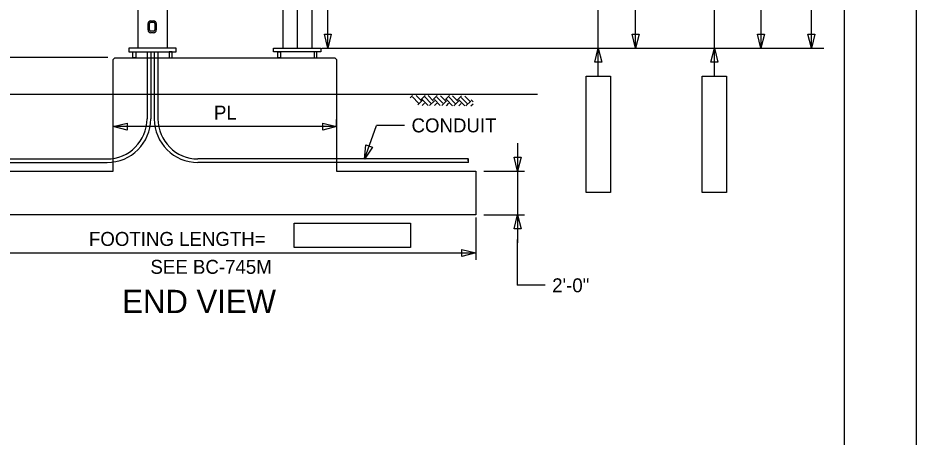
# Model space of a CAD drawing. Extents: x 3831399 to 3833095, y 499014 to 500202.
# Drawn here: x 3832893.8 to 3833081.2, y 499745.2 to 499832.5 of the extents above; entities that cross this region are included whole.
import ezdxf

# ---------------------------------------------------------------- set-up
doc = ezdxf.new("R2010")
doc.units = 0
for name, color, linetype in [('0-ANCHOR', 7, 'Continuous'), ('0-foundation', 7, 'Continuous'), ('0-truss', 7, 'Continuous'), ('2', 7, 'Continuous'), ('CenterLine', 7, 'Continuous'), ('Default', 7, 'Continuous'), ('DIM TXT', 7, 'Continuous'), ('PLT-BNDY', 7, 'Continuous'), ('structure', 7, 'Continuous'), ('XEG', 7, 'Continuous')]:
    doc.layers.add(name, color=color, linetype=linetype)

msp = doc.modelspace()

# ---------------------------------------------------------------- linework, layer by layer
at = {"layer": '0-ANCHOR'}
for p, q in [((3832917.82, 499825.49), (3832918.38, 499825.49)), ((3832917.82, 499824.26), (3832917.82, 499825.49)), ((3832918.38, 499825.49), (3832918.38, 499824.26)), ((3832925.97, 499825.49), (3832925.4, 499825.49)), ((3832925.4, 499825.49), (3832925.4, 499824.26)), ((3832925.97, 499824.26), (3832925.97, 499825.49)), ((3832948, 499825.49), (3832948.57, 499825.49)), ((3832948, 499824.26), (3832948, 499825.49)), ((3832948.57, 499825.49), (3832948.57, 499824.26)), ((3832956.16, 499825.49), (3832955.59, 499825.49)), ((3832955.59, 499825.49), (3832955.59, 499824.26)), ((3832956.16, 499824.26), (3832956.16, 499825.49)), ((3832918.38, 499824.26), (3832917.82, 499824.26)), ((3832925.4, 499824.26), (3832925.97, 499824.26)), ((3832948.57, 499824.26), (3832948, 499824.26)), ((3832955.59, 499824.26), (3832956.16, 499824.26))]:
    msp.add_line(p, q, dxfattribs=at)
at = {"layer": '0-foundation'}
for p, q in [((3832920.75, 499825.49), (3832920.75, 499811.51)), ((3832921.51, 499825.49), (3832921.51, 499811.51)), ((3832922.27, 499825.49), (3832922.27, 499811.51)), ((3832923.03, 499825.49), (3832923.03, 499811.51)), ((3832913.67, 499823.88), (3832914.05, 499824.26)), ((3832913.67, 499815.55), (3832913.67, 499823.88)), ((3832914.05, 499824.26), (3832959.92, 499824.26)), ((3832959.92, 499824.26), (3832960.3, 499823.88)), ((3832960.3, 499823.88), (3832960.3, 499815.55)), ((3832913.67, 499800.6), (3832913.67, 499815.55)), ((3832960.3, 499815.55), (3832960.3, 499800.6)), ((3832886.24, 499803.17), (3832912.41, 499803.17)), ((3832886.24, 499802.41), (3832912.41, 499802.41)), ((3832987.73, 499803.17), (3832931.37, 499803.17)), ((3832987.73, 499802.41), (3832931.37, 499802.41)), ((3832884.67, 499800.6), (3832913.67, 499800.6)), ((3832960.3, 499800.6), (3832989.31, 499800.6)), ((3832989.31, 499800.6), (3832989.31, 499791.5)), ((3832989.31, 499791.5), (3832884.67, 499791.5))]:
    msp.add_line(p, q, dxfattribs=at)
for centre, radius, start, end in [((3832912.41, 499811.51), 9.1, 270, 0), ((3832912.41, 499811.51), 8.34, 270, 0), ((3832931.37, 499811.51), 9.1, 180, 270), ((3832931.37, 499811.51), 8.34, 180, 270), ((3832987.87, 499802.98), 0.237, 126.8699, 233.1301), ((3832987.59, 499802.98), 0.237, 306.8699, 53.1301), ((3832987.59, 499802.6), 0.237, 306.8699, 53.1301)]:
    msp.add_arc(centre, radius, start, end, dxfattribs=at)
at = {"layer": '0-truss'}
for p, q in [((3832949.05, 499938.68), (3832949.05, 499826.25)), ((3832955.11, 499938.68), (3832955.11, 499826.25)), ((3832918.86, 499844.47), (3832918.86, 499826.25)), ((3832924.92, 499844.47), (3832924.92, 499826.25)), ((3832926.82, 499826.25), (3832916.96, 499826.25)), ((3832916.96, 499826.25), (3832916.96, 499825.49)), ((3832916.96, 499825.49), (3832926.82, 499825.49)), ((3832926.82, 499825.49), (3832926.82, 499826.25)), ((3832947.15, 499825.49), (3832947.15, 499826.25)), ((3832947.15, 499826.25), (3832957.01, 499826.25)), ((3832957.01, 499825.49), (3832947.15, 499825.49)), ((3832957.01, 499826.25), (3832957.01, 499825.49))]:
    msp.add_line(p, q, dxfattribs=at)
at = {"layer": '2'}
msp.add_line((3833066.16, 500187.03), (3833066.16, 499623.03), dxfattribs=at)
at = {"layer": 'CenterLine'}
msp.add_line((3832952.08, 499942.23), (3832952.08, 499826.25), dxfattribs=at)
at = {"layer": 'Default'}
for p, q in [((3833012.33, 499796.18), (3833012.33, 499820.43)), ((3833012.33, 499820.43), (3833017.42, 499820.43)), ((3833017.42, 499820.43), (3833017.42, 499796.18)), ((3833036.54, 499796.18), (3833036.54, 499820.43)), ((3833036.54, 499820.43), (3833041.63, 499820.43)), ((3833041.63, 499820.43), (3833041.63, 499796.18)), ((3833017.42, 499796.18), (3833012.33, 499796.18)), ((3833041.63, 499796.18), (3833036.54, 499796.18)), ((3832951.47, 499789.78), (3832975.72, 499789.78)), ((3832951.47, 499784.69), (3832951.47, 499789.78)), ((3832975.72, 499789.78), (3832975.72, 499784.69)), ((3832975.72, 499784.69), (3832951.47, 499784.69))]:
    msp.add_line(p, q, dxfattribs=at)
at = {"layer": 'DIM TXT'}
for p, q in [((3833022.67, 499826.25), (3833022.67, 499938.68)), ((3833048.79, 499938.68), (3833048.79, 499826.25)), ((3833059.34, 499826.25), (3833059.34, 499924.07)), ((3832958.46, 499826.25), (3832958.47, 499844.47)), ((3833014.87, 499826.25), (3833014.87, 499834.59)), ((3833039.09, 499826.25), (3833039.09, 499834.59)), ((3832957.19, 499826.25), (3833061.95, 499826.25)), ((3833014.87, 499820.43), (3833014.87, 499826.25)), ((3833039.09, 499820.43), (3833039.09, 499826.25)), ((3832912.59, 499824.28), (3832852.22, 499824.28)), ((3832911.14, 499824.28), (3832880.41, 499824.28)), ((3832913.67, 499809.89), (3832913.67, 499811.35)), ((3832960.3, 499809.89), (3832913.67, 499809.89)), ((3832960.3, 499809.89), (3832960.3, 499811.35)), ((3832966.1, 499803.13), (3832968.64, 499810.16)), ((3832974.46, 499810.16), (3832968.64, 499810.16)), ((3832998.05, 499806.42), (3832998.05, 499800.6)), ((3832991.03, 499800.6), (3832999.51, 499800.6)), ((3832998.05, 499800.6), (3832998.05, 499791.5)), ((3832998.05, 499796.05), (3832997.98, 499776.82)), ((3832989.31, 499790.98), (3832989.31, 499782.12)), ((3832991.03, 499791.5), (3832999.51, 499791.5)), ((3832998.05, 499791.5), (3832998.05, 499785.68)), ((3832884.67, 499783.58), (3832989.31, 499783.58)), ((3833003.8, 499776.82), (3832997.98, 499776.82))]:
    msp.add_line(p, q, dxfattribs=at)
for points in [[(3832959.19, 499829.16), (3832958.46, 499826.25), (3832957.74, 499829.16)], [(3833023.4, 499829.16), (3833022.67, 499826.25), (3833021.94, 499829.16)], [(3833049.52, 499829.16), (3833048.79, 499826.25), (3833048.07, 499829.16)], [(3833060.07, 499829.16), (3833059.34, 499826.25), (3833058.61, 499829.16)], [(3833014.14, 499823.34), (3833014.87, 499826.25), (3833015.6, 499823.34)], [(3833038.36, 499823.34), (3833039.09, 499826.25), (3833039.82, 499823.34)], [(3832916.58, 499809.17), (3832913.67, 499809.89), (3832916.58, 499810.62)], [(3832957.39, 499810.62), (3832960.3, 499809.89), (3832957.39, 499809.17)], [(3832967.77, 499805.62), (3832966.1, 499803.13), (3832966.4, 499806.11)], [(3832998.78, 499803.51), (3832998.05, 499800.6), (3832997.32, 499803.51)], [(3832997.32, 499788.59), (3832998.05, 499791.5), (3832998.78, 499788.59)], [(3832986.4, 499784.31), (3832989.31, 499783.58), (3832986.4, 499782.85)]]:
    msp.add_lwpolyline(points, close=True, dxfattribs=at)
at = {"layer": 'PLT-BNDY'}
msp.add_lwpolyline([(3832240.16, 500202.03), (3833081.16, 500202.03), (3833081.16, 499608.03), (3832240.16, 499608.03)], close=True, dxfattribs=at)
at = {"layer": 'structure'}
for p, q in [((3832920.98, 499830.05), (3832920.98, 499831.37)), ((3832921.26, 499830.05), (3832921.26, 499831.37)), ((3832921.54, 499831.94), (3832922.11, 499831.94)), ((3832921.54, 499831.66), (3832922.11, 499831.66)), ((3832922.4, 499831.37), (3832922.4, 499830.05)), ((3832922.68, 499831.37), (3832922.68, 499830.05)), ((3832922.11, 499829.76), (3832921.54, 499829.76)), ((3832922.11, 499829.48), (3832921.54, 499829.48))]:
    msp.add_line(p, q, dxfattribs=at)
for centre, radius, start, end in [((3832921.54, 499831.37), 0.569, 90, 180), ((3832921.54, 499831.37), 0.284, 90, 180), ((3832922.11, 499831.37), 0.569, 0, 90), ((3832922.11, 499831.37), 0.284, 0, 90), ((3832921.54, 499830.05), 0.569, 180, 270), ((3832921.54, 499830.05), 0.284, 180, 270), ((3832922.11, 499830.05), 0.569, 270, 0), ((3832922.11, 499830.05), 0.284, 270, 0)]:
    msp.add_arc(centre, radius, start, end, dxfattribs=at)
at = {"layer": 'XEG'}
for p, q in [((3832885.47, 499816.64), (3833002.21, 499816.64)), ((3832975.63, 499815.87), (3832976.16, 499816.38)), ((3832976.13, 499816.11), (3832977.39, 499814.82)), ((3832976.88, 499816.37), (3832977.9, 499815.32)), ((3832977.21, 499814.42), (3832978.15, 499815.33)), ((3832977.9, 499815.58), (3832978.74, 499816.39)), ((3832978.17, 499815.58), (3832979.4, 499814.31)), ((3832978.68, 499816.08), (3832979.94, 499814.8)), ((3832979.38, 499816.4), (3832980.45, 499815.3)), ((3832979.68, 499814.31), (3832980.69, 499815.29)), ((3832980.44, 499815.55), (3832981.29, 499816.38)), ((3832980.69, 499815.55), (3832981.93, 499814.28)), ((3832981.21, 499816.05), (3832982.46, 499814.76)), ((3832981.96, 499816.31), (3832982.98, 499815.27)), ((3832982.21, 499814.28), (3832983.23, 499815.27)), ((3832982.98, 499815.52), (3832983.84, 499816.36)), ((3832983.25, 499815.53), (3832984.49, 499814.25)), ((3832983.76, 499816.03), (3832985.02, 499814.74)), ((3832984.49, 499816.31), (3832985.53, 499815.24)), ((3832984.75, 499814.25), (3832985.77, 499815.24)), ((3832985.52, 499815.5), (3832986.32, 499816.28)), ((3832985.77, 499815.49), (3832987.02, 499814.22)), ((3832986.29, 499816), (3832987.54, 499814.71)), ((3832987.04, 499816.26), (3832988.06, 499815.21)), ((3832987.28, 499814.21), (3832988.3, 499815.21)), ((3832988.33, 499815.47), (3832988.76, 499815.03)), ((3832978.15, 499814.33), (3832978.65, 499814.81)), ((3832980.7, 499814.3), (3832981.19, 499814.78)), ((3832983.22, 499814.26), (3832983.73, 499814.76)), ((3832985.77, 499814.23), (3832986.27, 499814.72)), ((3832988.29, 499814.2), (3832988.75, 499814.65))]:
    msp.add_line(p, q, dxfattribs=at)

# ---------------------------------------------------------------- texts
at = {"layer": 'DIM TXT'}
for s, height, p in [('PL', 2.91, (3832934.71, 499811.35)), ('CONDUIT', 2.91, (3832975.92, 499808.7)), ('FOOTING LENGTH=     ', 2.9099, (3832908.63, 499785.03)), ('SEE BC-745M', 2.9099, (3832921.46, 499779.21)), ('2\'-0"', 2.91, (3833005.26, 499775.36)), ('END VIEW', 4.85, (3832915.58, 499771.03))]:
    msp.add_text(s, height=height, dxfattribs=at).set_placement(p)

doc.saveas('drawing.dxf')
